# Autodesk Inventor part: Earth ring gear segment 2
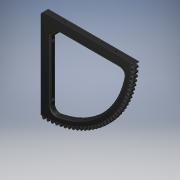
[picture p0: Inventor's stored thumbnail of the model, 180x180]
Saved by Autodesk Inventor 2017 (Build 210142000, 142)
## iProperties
Created: 2016-08
Part Number: Earth ring gear segment 2
Material: Generic
Document SubType Name: Modeling
Designer: Stan
Density: 1 g/cm^3
Appearance: Glossy - Black
Author: Stan
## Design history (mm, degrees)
sketch "Sketch1"
  geometry: L1 (0, -115.696)-(0, -3.175); L2 (3.175, 0)-(119.081, 0); L3 (12.7, -21.997)-(12.7, -99.798); L4 (99.798, -12.7)-(21.997, -12.7); A1 r 1.272 centre (117.809, 0) between (118.123, -1.232) and (119.081, 0); A2 r 27.123 centre (112.999, 25.402) between (115.686, -1.587) and (118.123, -1.232); A3 r 1.272 centre (2.762, -117.777) between (1.537, -118.12) and (4.001, -118.062); A4 r 27.123 centre (-22.746, -113.563) between (4.001, -118.062) and (4.299, -115.617); A5 r 27.123 centre (28.044, -112.372) between (1.125, -115.691) and (1.537, -118.12); A6 r 1.272 centre (8.279, -117.518) between (7.072, -117.918) and (9.531, -117.745); A7 r 27.123 centre (-17.398, -114.504) between (9.531, -117.745) and (9.713, -115.288); A8 r 27.123 centre (33.28, -110.934) between (6.546, -115.511) and (7.072, -117.918); A9 r 1.272 centre (13.778, -117.001) between (12.591, -117.457) and (15.039, -117.169); A10 r 27.123 centre (-12.012, -115.194) between (15.039, -117.169) and (15.107, -114.706); A11 r 27.123 centre (38.443, -109.252) between (11.953, -115.077) and (12.591, -117.457); A12 r 1.272 centre (19.247, -116.226) between (18.083, -116.738) and (20.514, -116.335); A13 r 27.123 centre (-6.599, -115.631) between (20.514, -116.335) and (20.467, -113.872); A14 r 27.123 centre (43.522, -107.33) between (17.334, -114.391) and (18.083, -116.738); A15 r 1.272 centre (24.674, -115.196) between (23.535, -115.762) and (25.945, -115.246); A16 r 27.123 centre (-1.172, -115.813) between (25.945, -115.246) and (25.781, -112.787); A17 r 27.123 centre (48.505, -105.172) between (22.677, -113.452) and (23.535, -115.762); A18 r 1.272 centre (30.046, -113.913) between (28.935, -114.531) and (31.318, -113.903); A19 r 27.123 centre (4.258, -115.74) between (31.318, -113.903) and (31.04, -111.455); A20 r 27.123 centre (53.381, -102.783) between (27.97, -112.265) and (28.935, -114.531); A21 r 1.272 centre (35.353, -112.38) between (34.272, -113.049) and (36.623, -112.31); A22 r 27.123 centre (9.678, -115.414) between (36.623, -112.31) and (36.23, -109.878); A23 r 27.123 centre (58.14, -100.168) between (33.201, -110.83) and (34.272, -113.049); A24 r 1.272 centre (40.581, -110.599) between (39.533, -111.319) and (41.847, -110.47); A25 r 27.123 centre (15.077, -114.833) between (41.847, -110.47) and (41.34, -108.059); A26 r 27.123 centre (62.772, -97.333) between (38.36, -109.152) and (39.533, -111.319); A27 r 1.272 centre (45.721, -108.575) between (44.707, -109.343) and (46.978, -108.387); A28 r 27.123 centre (20.443, -114) between (46.978, -108.387) and (46.36, -106.002); A29 r 27.123 centre (67.265, -94.284) between (43.434, -107.234) and (44.707, -109.343); A30 r 1.272 centre (50.76, -106.313) between (49.783, -107.128) and (52.007, -106.066); A31 r 27.123 centre (25.764, -112.917) between (52.007, -106.066) and (51.277, -103.713); A32 r 27.123 centre (71.61, -91.027) between (48.412, -105.081) and (49.783, -107.128); A33 r 1.272 centre (55.687, -103.817) between (54.75, -104.676) and (56.922, -103.511); A34 r 27.123 centre (31.028, -111.585) between (56.922, -103.511) and (56.082, -101.195); A35 r 27.123 centre (75.798, -87.571) between (53.284, -102.696) and (54.75, -104.676); A36 r 1.272 centre (60.492, -101.093) between (59.596, -101.995) and (61.711, -100.73); A37 r 27.123 centre (36.224, -110.008) between (61.711, -100.73) and (60.764, -98.455); A38 r 27.123 centre (79.819, -83.921) between (58.039, -100.085) and (59.596, -101.995); A39 r 1.272 centre (65.164, -98.146) between (64.311, -99.09) and (66.364, -97.726); A40 r 27.123 centre (41.341, -108.189) between (66.364, -97.726) and (65.312, -95.499); A41 r 27.123 centre (83.665, -80.088) between (62.667, -97.255) and (64.311, -99.09); A42 r 1.272 centre (69.693, -94.984) between (68.885, -95.966) and (70.872, -94.508); A43 r 27.123 centre (46.366, -106.133) between (70.872, -94.508) and (69.716, -92.333); A44 r 27.123 centre (87.327, -76.078) between (67.156, -94.211) and (68.885, -95.966); A45 r 1.272 centre (74.068, -91.613) between (73.307, -92.632) and (75.224, -91.082); A46 r 27.123 centre (51.29, -103.843) between (75.224, -91.082) and (73.967, -88.963); A47 r 27.123 centre (90.797, -71.901) between (71.499, -90.959) and (73.307, -92.632); A48 r 1.272 centre (78.281, -88.04) between (77.569, -89.094) and (79.411, -87.456); A49 r 27.123 centre (56.101, -101.324) between (79.411, -87.456) and (78.056, -85.399); A50 r 27.123 centre (94.068, -67.567) between (75.683, -87.508) and (77.569, -89.094); A51 r 1.272 centre (82.321, -84.274) between (81.66, -85.36) and (83.423, -83.638); A52 r 27.123 centre (60.789, -98.583) between (83.423, -83.638) and (81.973, -81.646); A53 r 27.123 centre (97.131, -63.083) between (79.702, -83.865) and (81.66, -85.36); A54 r 1.272 centre (86.181, -80.323) between (85.571, -81.439) and (87.251, -79.636); A55 r 27.123 centre (65.343, -95.626) between (87.251, -79.636) and (85.71, -77.714); A56 r 27.123 centre (99.981, -58.461) between (83.545, -80.037) and (85.571, -81.439); A57 r 1.272 centre (89.851, -76.195) between (89.294, -77.339) and (90.888, -75.459); A58 r 27.123 centre (69.753, -92.458) between (90.888, -75.459) and (89.258, -73.611); A59 r 27.123 centre (102.612, -53.71) between (87.205, -76.033) and (89.294, -77.339); A60 r 1.272 centre (93.324, -71.9) between (92.821, -73.068) and (94.325, -71.116); A61 r 27.123 centre (74.01, -89.087) between (94.325, -71.116) and (92.611, -69.347); A62 r 27.123 centre (105.016, -48.842) between (90.673, -71.862) and (92.821, -73.068); A63 r 1.272 centre (96.591, -67.447) between (96.144, -68.637) and (97.555, -66.616); A64 r 27.123 centre (78.105, -85.52) between (97.555, -66.616) and (95.759, -64.929)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; 1 further point
  constraints: 206 point on circle, 103 centre point, 8 end point, 111 other
extrude "Extrusion1" new body sketch "Sketch1" distance "d0" = 6.35; taper "d1" = 0 deg
sketch "Sketch2"
  geometry: L1 (0, 77.801)-(-6.35, 77.801) reference; L2 (0, 0)-(-6.35, 0) reference; L3 (0, 77.801)-(0, 0) reference; C1 r 1.587 at (-3.175, 71.451); C2 r 1.588 at (-3.175, 6.35); 1 further point
  constraints: 2 centre point
  dimensions: "d2" = 3.175 diameter of C1; "d3" = 3.175 diameter of C2; "d4" = 6.35 distance from line of L1 C1.centre; "d5" = 6.35 distance from line of L2 C2.centre; "d6" = 3.175 distance from line of C1.centre L3; "d7" = 3.175 distance from line of C2.centre L3
extrude "Extrusion2" cut sketch "Sketch2" distance "d8" = 12.7; taper "d9" = 0 deg
sketch "Sketch3"
  geometry: L1 (77.801, 0)-(77.801, 6.35) reference; L2 (0, 0)-(0, 6.35) reference; L3 (0, 6.35)-(77.801, 6.35) reference; C1 r 1.587 at (71.451, 3.175); C2 r 1.587 at (6.35, 3.175); 1 further point
  constraints: 2 centre point
  dimensions: "d10" = 3.175 diameter of C1; "d11" = 3.175 diameter of C2; "d12" = 6.35 distance from line of C1.centre L1; "d13" = 6.35 distance from line of C2.centre L2; "d14" = 3.175 distance from line of C1.centre L3; "d15" = 3.175 distance from line of L3 C2.centre
extrude "Extrusion3" cut sketch "Sketch3" distance "d16" = 12.7; taper "d17" = 0 deg
fillet "Fillet1" dims "d18" = 0.79375
fillet "Fillet2" dims "d19" = 0.79375
fillet "Fillet3" dims "d20" = 0.79375
fillet "Fillet4" dims "d21" = 0.79375
fillet "Fillet5" dims "d22" = 0.79375
fillet "Fillet6" dims "d23" = 0.79375
fillet "Fillet7" dims "d24" = 0.79375
fillet "Fillet8" dims "d25" = 0.79375
fillet "Fillet9" dims "d26" = 1.5875
body "Solid1"
